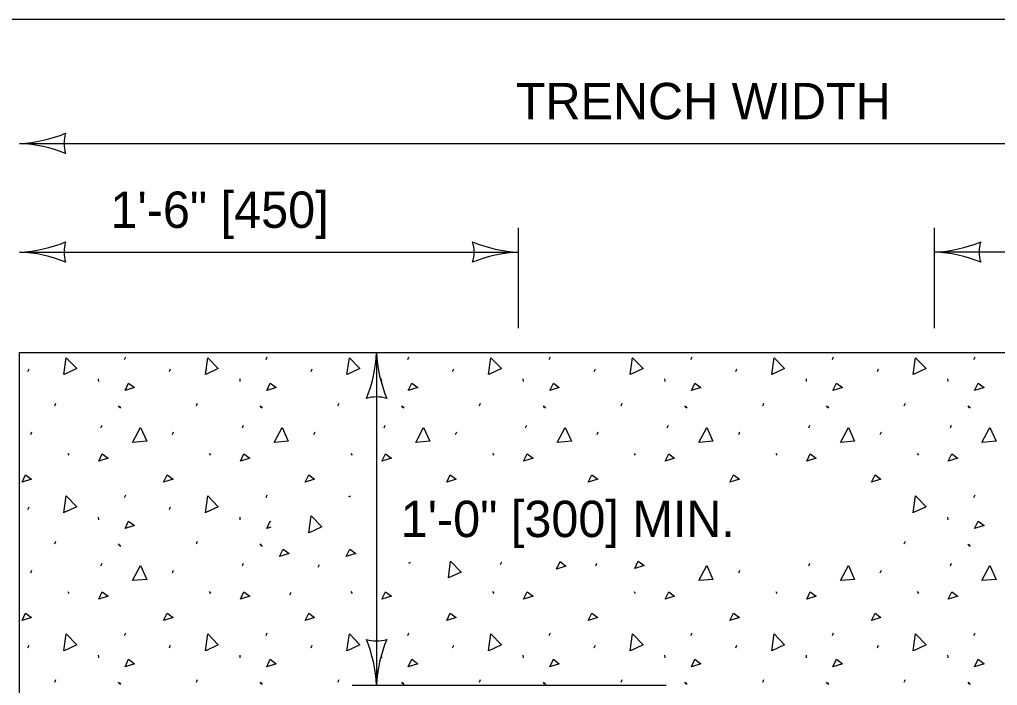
# Model space of a CAD drawing. Extents: x 49991.4 to 50061.4, y 49960.6 to 50011.4.
# Drawn here: x 50012.414 to 50014.03, y 49996.543 to 49997.642 of the extents above; entities that cross this region are included whole.
import ezdxf

# ---------------------------------------------------------------- set-up
doc = ezdxf.new("R2010")
doc.units = 0
for name, color, linetype in [('Level 1', 7, 'Continuous'), ('Level 2', 7, 'Continuous'), ('Level 3', 7, 'Continuous')]:
    doc.layers.add(name, color=color, linetype=linetype)

msp = doc.modelspace()

# ---------------------------------------------------------------- linework, layer by layer
at = {"layer": 'Level 1'}
for p, q in [((50015.4944, 49997.6424), (50011.6711, 49997.6424)), ((50012.4143, 49997.0926), (50014.7511, 49997.0926)), ((50012.4143, 49995.58), (50012.4143, 49997.0926)), ((50012.5878, 49997.0811), (50012.5897, 49997.0855)), ((50012.8217, 49997.0811), (50012.8237, 49997.0855)), ((50013.0557, 49997.0811), (50013.0576, 49997.0855)), ((50013.2896, 49997.0811), (50013.2916, 49997.0855)), ((50013.5236, 49997.0811), (50013.5256, 49997.0855)), ((50013.7576, 49997.0811), (50013.7595, 49997.0855)), ((50013.9915, 49997.0811), (50013.9935, 49997.0855)), ((50012.4281, 49997.0611), (50012.43, 49997.0655)), ((50012.662, 49997.0611), (50012.664, 49997.0655)), ((50012.896, 49997.0611), (50012.8979, 49997.0655)), ((50013.1299, 49997.0611), (50013.1319, 49997.0655)), ((50013.3639, 49997.0611), (50013.3658, 49997.0655)), ((50013.5978, 49997.0611), (50013.5998, 49997.0655)), ((50013.8318, 49997.0611), (50013.8337, 49997.0655)), ((50012.5442, 49997.0488), (50012.5447, 49997.0444)), ((50012.7781, 49997.0488), (50012.7786, 49997.0444)), ((50013.0121, 49997.0488), (50013.0126, 49997.0444)), ((50013.246, 49997.0488), (50013.2465, 49997.0444)), ((50013.48, 49997.0488), (50013.4805, 49997.0444)), ((50013.714, 49997.0488), (50013.7144, 49997.0444)), ((50013.9479, 49997.0488), (50013.9484, 49997.0444)), ((50012.4725, 49997.0044), (50012.4744, 49997.0088)), ((50012.5775, 49997.0044), (50012.5795, 49997.0015)), ((50012.5795, 49997.0033), (50012.5814, 49997.0004)), ((50012.7065, 49997.0044), (50012.7084, 49997.0088)), ((50012.8115, 49997.0044), (50012.8134, 49997.0015)), ((50012.8134, 49997.0033), (50012.8154, 49997.0004)), ((50012.9404, 49997.0044), (50012.9424, 49997.0088)), ((50013.0454, 49997.0044), (50013.0474, 49997.0015)), ((50013.0474, 49997.0033), (50013.0493, 49997.0004)), ((50013.1744, 49997.0044), (50013.1763, 49997.0088)), ((50013.2794, 49997.0044), (50013.2813, 49997.0015)), ((50013.2813, 49997.0033), (50013.2833, 49997.0004)), ((50013.4083, 49997.0044), (50013.4103, 49997.0088)), ((50013.5133, 49997.0044), (50013.5153, 49997.0015)), ((50013.5153, 49997.0033), (50013.5172, 49997.0004)), ((50013.6423, 49997.0044), (50013.6442, 49997.0088)), ((50013.7473, 49997.0044), (50013.7493, 49997.0015)), ((50013.7493, 49997.0033), (50013.7512, 49997.0004)), ((50013.8762, 49997.0044), (50013.8782, 49997.0088)), ((50013.9813, 49997.0044), (50013.9832, 49997.0015)), ((50013.9832, 49997.0033), (50013.9852, 49997.0004)), ((50012.5487, 49996.9682), (50012.5506, 49996.9726)), ((50012.7826, 49996.9682), (50012.7846, 49996.9726)), ((50013.0166, 49996.9682), (50013.0186, 49996.9726)), ((50013.2506, 49996.9682), (50013.2525, 49996.9726)), ((50013.4845, 49996.9682), (50013.4865, 49996.9726)), ((50013.7185, 49996.9682), (50013.7204, 49996.9726)), ((50013.9524, 49996.9682), (50013.9544, 49996.9726)), ((50012.4329, 49996.957), (50012.4349, 49996.9614)), ((50012.6669, 49996.957), (50012.6688, 49996.9614)), ((50012.9008, 49996.957), (50012.9028, 49996.9614)), ((50013.1348, 49996.957), (50013.1368, 49996.9614)), ((50013.3688, 49996.957), (50013.3707, 49996.9614)), ((50013.6027, 49996.957), (50013.6047, 49996.9614)), ((50013.8367, 49996.957), (50013.8386, 49996.9614)), ((50012.494, 49996.9257), (50012.4959, 49996.9228)), ((50012.7279, 49996.9257), (50012.7299, 49996.9228)), ((50012.9619, 49996.9257), (50012.9639, 49996.9228)), ((50013.1959, 49996.9257), (50013.1978, 49996.9228)), ((50013.4298, 49996.9257), (50013.4318, 49996.9228)), ((50013.6638, 49996.9257), (50013.6657, 49996.9228)), ((50013.8977, 49996.9257), (50013.8997, 49996.9228)), ((50012.5878, 49996.853), (50012.5897, 49996.8573)), ((50012.8217, 49996.853), (50012.8237, 49996.8573)), ((50013.9915, 49996.853), (50013.9935, 49996.8573)), ((50012.4281, 49996.8329), (50012.43, 49996.8373)), ((50012.662, 49996.8329), (50012.664, 49996.8373)), ((50012.5442, 49996.8207), (50012.5447, 49996.8163)), ((50012.7781, 49996.8207), (50012.7786, 49996.8163)), ((50013.9479, 49996.8207), (50013.9484, 49996.8163)), ((50012.4725, 49996.7763), (50012.4744, 49996.7807)), ((50012.5775, 49996.7763), (50012.5795, 49996.7733)), ((50012.5795, 49996.7752), (50012.5814, 49996.7722)), ((50012.7065, 49996.7763), (50012.7084, 49996.7807)), ((50012.8115, 49996.7763), (50012.8134, 49996.7733)), ((50012.8134, 49996.7752), (50012.8154, 49996.7722)), ((50013.8762, 49996.7763), (50013.8782, 49996.7807)), ((50013.9813, 49996.7763), (50013.9832, 49996.7733)), ((50013.9832, 49996.7752), (50013.9852, 49996.7722)), ((50012.5487, 49996.7401), (50012.5506, 49996.7445)), ((50012.7826, 49996.7401), (50012.7846, 49996.7445)), ((50012.908, 49996.738), (50012.91, 49996.7424)), ((50013.2092, 49996.7421), (50013.2111, 49996.7465)), ((50013.3666, 49996.7399), (50013.3685, 49996.7443)), ((50013.7185, 49996.7401), (50013.7204, 49996.7445)), ((50013.9524, 49996.7401), (50013.9544, 49996.7445)), ((50012.4329, 49996.7288), (50012.4349, 49996.7332)), ((50012.6669, 49996.7288), (50012.6688, 49996.7332)), ((50013.6027, 49996.7288), (50013.6047, 49996.7332)), ((50013.8367, 49996.7288), (50013.8386, 49996.7332)), ((50012.494, 49996.6976), (50012.4959, 49996.6946)), ((50012.7279, 49996.6976), (50012.7299, 49996.6946)), ((50012.8611, 49996.6922), (50012.8631, 49996.6966)), ((50012.9619, 49996.6976), (50012.9639, 49996.6946)), ((50013.1959, 49996.6976), (50013.1978, 49996.6946)), ((50013.4298, 49996.6976), (50013.4318, 49996.6946)), ((50013.6638, 49996.6976), (50013.6657, 49996.6946)), ((50013.8977, 49996.6976), (50013.8997, 49996.6946)), ((50012.5878, 49996.6248), (50012.5897, 49996.6292)), ((50012.8217, 49996.6248), (50012.8237, 49996.6292)), ((50013.0557, 49996.6248), (50013.0576, 49996.6292)), ((50013.2896, 49996.6248), (50013.2916, 49996.6292)), ((50013.5236, 49996.6248), (50013.5256, 49996.6292)), ((50013.7576, 49996.6248), (50013.7595, 49996.6292)), ((50013.9915, 49996.6248), (50013.9935, 49996.6292)), ((50012.4281, 49996.6048), (50012.43, 49996.6092)), ((50012.662, 49996.6048), (50012.664, 49996.6092)), ((50012.896, 49996.6048), (50012.8979, 49996.6092)), ((50013.1299, 49996.6048), (50013.1319, 49996.6092)), ((50013.3639, 49996.6048), (50013.3658, 49996.6092)), ((50013.5978, 49996.6048), (50013.5998, 49996.6092)), ((50013.8318, 49996.6048), (50013.8337, 49996.6092)), ((50012.5442, 49996.5925), (50012.5447, 49996.5881)), ((50012.7781, 49996.5925), (50012.7786, 49996.5881)), ((50013.0121, 49996.5925), (50013.0126, 49996.5881)), ((50013.246, 49996.5925), (50013.2465, 49996.5881)), ((50013.48, 49996.5925), (50013.4805, 49996.5881)), ((50013.714, 49996.5925), (50013.7144, 49996.5881)), ((50013.9479, 49996.5925), (50013.9484, 49996.5881)), ((50012.4725, 49996.5481), (50012.4744, 49996.5525)), ((50012.5775, 49996.5481), (50012.5795, 49996.5452)), ((50012.7065, 49996.5481), (50012.7084, 49996.5525)), ((50012.8115, 49996.5481), (50012.8134, 49996.5452)), ((50012.9404, 49996.5481), (50012.9424, 49996.5525)), ((50013.0454, 49996.5481), (50013.0474, 49996.5452)), ((50013.1744, 49996.5481), (50013.1763, 49996.5525)), ((50013.2794, 49996.5481), (50013.2813, 49996.5452)), ((50013.4083, 49996.5481), (50013.4103, 49996.5525)), ((50013.5133, 49996.5481), (50013.5153, 49996.5452)), ((50013.6423, 49996.5481), (50013.6442, 49996.5525)), ((50013.7473, 49996.5481), (50013.7493, 49996.5452)), ((50013.8762, 49996.5481), (50013.8782, 49996.5525)), ((50013.9813, 49996.5481), (50013.9832, 49996.5452)), ((50012.5795, 49996.547), (50012.5814, 49996.5441)), ((50012.8134, 49996.547), (50012.8154, 49996.5441)), ((50013.0474, 49996.547), (50013.0493, 49996.5441)), ((50013.2813, 49996.547), (50013.2833, 49996.5441)), ((50013.5153, 49996.547), (50013.5172, 49996.5441)), ((50013.7493, 49996.547), (50013.7512, 49996.5441)), ((50013.9832, 49996.547), (50013.9852, 49996.5441))]:
    msp.add_line(p, q, dxfattribs=at)
for points in [[(50012.4875, 49997.056), (50012.4913, 49997.0839), (50012.5088, 49997.0659), (50012.4879, 49997.0562)], [(50012.7214, 49997.056), (50012.7253, 49997.0839), (50012.7428, 49997.0659), (50012.7219, 49997.0562)], [(50012.9554, 49997.056), (50012.9593, 49997.0839), (50012.9767, 49997.0659), (50012.9558, 49997.0562)], [(50013.1893, 49997.056), (50013.1932, 49997.0839), (50013.2107, 49997.0659), (50013.1898, 49997.0562)], [(50013.4233, 49997.056), (50013.4272, 49997.0839), (50013.4447, 49997.0659), (50013.4238, 49997.0562)], [(50013.6573, 49997.056), (50013.6611, 49997.0839), (50013.6786, 49997.0659), (50013.6577, 49997.0562)], [(50013.8912, 49997.056), (50013.8951, 49997.0839), (50013.9126, 49997.0659), (50013.8917, 49997.0562)], [(50012.5887, 49997.0298), (50012.5946, 49997.042), (50012.6044, 49997.0347), (50012.5887, 49997.0298)], [(50012.8227, 49997.0298), (50012.8286, 49997.042), (50012.8383, 49997.0347), (50012.8227, 49997.0298)], [(50013.0567, 49997.0298), (50013.0625, 49997.042), (50013.0723, 49997.0347), (50013.0567, 49997.0298)], [(50013.2906, 49997.0298), (50013.2965, 49997.042), (50013.3062, 49997.0347), (50013.2906, 49997.0298)], [(50013.5246, 49997.0298), (50013.5304, 49997.042), (50013.5402, 49997.0347), (50013.5246, 49997.0298)], [(50013.7585, 49997.0298), (50013.7644, 49997.042), (50013.7742, 49997.0347), (50013.7585, 49997.0298)], [(50013.9925, 49997.0298), (50013.9984, 49997.042), (50014.0081, 49997.0347), (50013.9925, 49997.0298)], [(50012.601, 49996.9438), (50012.6141, 49996.9687), (50012.6244, 49996.9458), (50012.6014, 49996.9438)], [(50012.8349, 49996.9438), (50012.8481, 49996.9687), (50012.8584, 49996.9458), (50012.8354, 49996.9438)], [(50013.0689, 49996.9438), (50013.0821, 49996.9687), (50013.0923, 49996.9458), (50013.0694, 49996.9438)], [(50013.3028, 49996.9438), (50013.316, 49996.9687), (50013.3263, 49996.9458), (50013.3033, 49996.9438)], [(50013.5368, 49996.9438), (50013.55, 49996.9687), (50013.5602, 49996.9458), (50013.5373, 49996.9438)], [(50013.7707, 49996.9438), (50013.7839, 49996.9687), (50013.7942, 49996.9458), (50013.7712, 49996.9438)], [(50014.0047, 49996.9438), (50014.0179, 49996.9687), (50014.0281, 49996.9458), (50014.0052, 49996.9438)], [(50012.5453, 49996.913), (50012.5511, 49996.9252), (50012.5609, 49996.9179), (50012.5453, 49996.913)], [(50012.7792, 49996.913), (50012.7851, 49996.9252), (50012.7949, 49996.9179), (50012.7792, 49996.913)], [(50013.0132, 49996.913), (50013.019, 49996.9252), (50013.0288, 49996.9179), (50013.0132, 49996.913)], [(50013.2471, 49996.913), (50013.253, 49996.9252), (50013.2628, 49996.9179), (50013.2471, 49996.913)], [(50013.4811, 49996.913), (50013.487, 49996.9252), (50013.4967, 49996.9179), (50013.4811, 49996.913)], [(50013.7151, 49996.913), (50013.7209, 49996.9252), (50013.7307, 49996.9179), (50013.7151, 49996.913)], [(50013.949, 49996.913), (50013.9549, 49996.9252), (50013.9646, 49996.9179), (50013.949, 49996.913)], [(50012.4184, 49996.8781), (50012.4242, 49996.8903), (50012.434, 49996.883), (50012.4184, 49996.8781)], [(50012.6523, 49996.8781), (50012.6582, 49996.8903), (50012.668, 49996.883), (50012.6523, 49996.8781)], [(50012.8863, 49996.8781), (50012.8922, 49996.8903), (50012.9019, 49996.883), (50012.8863, 49996.8781)], [(50013.1203, 49996.8781), (50013.1261, 49996.8903), (50013.1359, 49996.883), (50013.1203, 49996.8781)], [(50013.3542, 49996.8781), (50013.3601, 49996.8903), (50013.3698, 49996.883), (50013.3542, 49996.8781)], [(50013.5882, 49996.8781), (50013.594, 49996.8903), (50013.6038, 49996.883), (50013.5882, 49996.8781)], [(50013.8221, 49996.8781), (50013.828, 49996.8903), (50013.8378, 49996.883), (50013.8221, 49996.8781)], [(50012.4875, 49996.8279), (50012.4913, 49996.8558), (50012.5088, 49996.8377), (50012.4879, 49996.828)], [(50012.7214, 49996.8279), (50012.7253, 49996.8558), (50012.7428, 49996.8377), (50012.7219, 49996.828)], [(50012.959, 49996.8543), (50012.9593, 49996.8558), (50012.9607, 49996.8543)], [(50013.8912, 49996.8279), (50013.8951, 49996.8558), (50013.9126, 49996.8377), (50013.8917, 49996.828)], [(50012.8922, 49996.7946), (50012.8961, 49996.8225), (50012.9136, 49996.8044), (50012.8927, 49996.7948)], [(50012.5887, 49996.8017), (50012.5946, 49996.8139), (50012.6044, 49996.8066), (50012.5887, 49996.8017)], [(50012.8227, 49996.8017), (50012.8286, 49996.8139), (50012.8295, 49996.8132)], [(50013.9925, 49996.8017), (50013.9984, 49996.8139), (50014.0081, 49996.8066), (50013.9925, 49996.8017)], [(50012.8295, 49996.8038), (50012.8227, 49996.8017)], [(50012.8441, 49996.7556), (50012.85, 49996.7678), (50012.8597, 49996.7604), (50012.8441, 49996.7556)], [(50012.9541, 49996.7556), (50012.96, 49996.7678), (50012.9698, 49996.7604), (50012.9541, 49996.7556)], [(50013.0583, 49996.7445), (50013.0585, 49996.746), (50013.06, 49996.7445)], [(50013.1229, 49996.7201), (50013.1267, 49996.748), (50013.1442, 49996.7299), (50013.1233, 49996.7202)], [(50013.3016, 49996.7347), (50013.3075, 49996.747), (50013.3172, 49996.7396), (50013.3016, 49996.7347)], [(50013.4309, 49996.7358), (50013.4367, 49996.748), (50013.4465, 49996.7407), (50013.4309, 49996.7358)], [(50012.601, 49996.7157), (50012.6141, 49996.7406), (50012.6244, 49996.7176), (50012.6014, 49996.7157)], [(50013.5368, 49996.7157), (50013.55, 49996.7406), (50013.5602, 49996.7176), (50013.5373, 49996.7157)], [(50013.7707, 49996.7157), (50013.7839, 49996.7406), (50013.7942, 49996.7176), (50013.7712, 49996.7157)], [(50014.0047, 49996.7157), (50014.0179, 49996.7406), (50014.0281, 49996.7176), (50014.0052, 49996.7157)], [(50012.5453, 49996.6849), (50012.5511, 49996.6971), (50012.5609, 49996.6898), (50012.5453, 49996.6849)], [(50012.7792, 49996.6849), (50012.7851, 49996.6971), (50012.7949, 49996.6898), (50012.7792, 49996.6849)], [(50013.0132, 49996.6849), (50013.019, 49996.6971), (50013.0288, 49996.6898), (50013.0132, 49996.6849)], [(50013.2471, 49996.6849), (50013.253, 49996.6971), (50013.2628, 49996.6898), (50013.2471, 49996.6849)], [(50013.4811, 49996.6849), (50013.487, 49996.6971), (50013.4967, 49996.6898), (50013.4811, 49996.6849)], [(50013.7151, 49996.6849), (50013.7209, 49996.6971), (50013.7307, 49996.6898), (50013.7151, 49996.6849)], [(50013.949, 49996.6849), (50013.9549, 49996.6971), (50013.9646, 49996.6898), (50013.949, 49996.6849)], [(50012.4184, 49996.65), (50012.4242, 49996.6622), (50012.434, 49996.6549), (50012.4184, 49996.65)], [(50012.6523, 49996.65), (50012.6582, 49996.6622), (50012.668, 49996.6549), (50012.6523, 49996.65)], [(50012.8863, 49996.65), (50012.8922, 49996.6622), (50012.9019, 49996.6549), (50012.8863, 49996.65)], [(50013.1203, 49996.65), (50013.1261, 49996.6622), (50013.1359, 49996.6549), (50013.1203, 49996.65)], [(50013.3542, 49996.65), (50013.3601, 49996.6622), (50013.3698, 49996.6549), (50013.3542, 49996.65)], [(50013.5882, 49996.65), (50013.594, 49996.6622), (50013.6038, 49996.6549), (50013.5882, 49996.65)], [(50013.8221, 49996.65), (50013.828, 49996.6622), (50013.8378, 49996.6549), (50013.8221, 49996.65)], [(50012.4875, 49996.5997), (50012.4913, 49996.6276), (50012.5088, 49996.6096), (50012.4879, 49996.5999)], [(50012.7214, 49996.5997), (50012.7253, 49996.6276), (50012.7428, 49996.6096), (50012.7219, 49996.5999)], [(50012.9554, 49996.5997), (50012.9593, 49996.6276), (50012.9767, 49996.6096), (50012.9558, 49996.5999)], [(50013.1893, 49996.5997), (50013.1932, 49996.6276), (50013.2107, 49996.6096), (50013.1898, 49996.5999)], [(50013.4233, 49996.5997), (50013.4272, 49996.6276), (50013.4447, 49996.6096), (50013.4238, 49996.5999)], [(50013.6573, 49996.5997), (50013.6611, 49996.6276), (50013.6786, 49996.6096), (50013.6577, 49996.5999)], [(50013.8912, 49996.5997), (50013.8951, 49996.6276), (50013.9126, 49996.6096), (50013.8917, 49996.5999)], [(50012.5887, 49996.5735), (50012.5946, 49996.5857), (50012.6044, 49996.5784), (50012.5887, 49996.5735)], [(50012.8227, 49996.5735), (50012.8286, 49996.5857), (50012.8383, 49996.5784), (50012.8227, 49996.5735)], [(50013.0567, 49996.5735), (50013.0625, 49996.5857), (50013.0723, 49996.5784), (50013.0567, 49996.5735)], [(50013.2906, 49996.5735), (50013.2965, 49996.5857), (50013.3062, 49996.5784), (50013.2906, 49996.5735)], [(50013.5246, 49996.5735), (50013.5304, 49996.5857), (50013.5402, 49996.5784), (50013.5246, 49996.5735)], [(50013.7585, 49996.5735), (50013.7644, 49996.5857), (50013.7742, 49996.5784), (50013.7585, 49996.5735)], [(50013.9925, 49996.5735), (50013.9984, 49996.5857), (50014.0081, 49996.5784), (50013.9925, 49996.5735)]]:
    msp.add_lwpolyline(points, dxfattribs=at)
at = {"layer": 'Level 3'}
for p, q in [((50012.4143, 49997.4378), (50014.7511, 49997.4378)), ((50013.239, 49997.1326), (50013.239, 49997.2983)), ((50013.9265, 49997.1326), (50013.9265, 49997.2983)), ((50012.4143, 49997.2583), (50013.239, 49997.2583)), ((50014.7511, 49997.2583), (50013.9265, 49997.2583)), ((50013.0042, 49997.0926), (50013.0042, 49996.5426)), ((50013.4827, 49996.5426), (50012.9642, 49996.5426))]:
    msp.add_line(p, q, dxfattribs=at)
for centre, radius, start, end in [((50012.4029, 49997.6705), 0.233, 272.8273, 292.0772), ((50012.5426, 49997.4378), 0.0548, 162.1388, 197.8612), ((50012.4052, 49997.2156), 0.2223, 67.456, 87.6395), ((50012.4029, 49997.491), 0.233, 272.8273, 292.0772), ((50012.5426, 49997.2583), 0.0548, 162.1388, 197.8612), ((50013.2481, 49997.4804), 0.2223, 247.456, 267.6395), ((50013.1108, 49997.2583), 0.0548, 342.1388, 17.8612), ((50013.915, 49997.491), 0.233, 272.8273, 292.0772), ((50014.0547, 49997.2583), 0.0548, 162.1388, 197.8612), ((50012.4052, 49997.0362), 0.2223, 67.456, 87.6395), ((50013.2505, 49997.0256), 0.233, 92.8273, 112.0772), ((50013.9173, 49997.0362), 0.2223, 67.456, 87.6395), ((50012.7821, 49997.1017), 0.2223, 337.456, 357.6395), ((50013.2369, 49997.1041), 0.233, 182.8273, 202.0772), ((50013.0042, 49996.9643), 0.0548, 72.1388, 107.8612), ((50013.0042, 49996.6708), 0.0548, 252.1388, 287.8612), ((50012.7715, 49996.5311), 0.233, 2.8273, 22.0772), ((50013.2264, 49996.5334), 0.2223, 157.456, 177.6395)]:
    msp.add_arc(centre, radius, start, end, dxfattribs=at)

# ---------------------------------------------------------------- texts
at = {"layer": 'Level 2'}
for s, p in [('TRENCH WIDTH', (50013.2344, 49997.4778)), ('1\'-6" [450]', (50012.5646, 49997.2983)), ('1\'-0" [300] MIN.', (50013.0442, 49996.7876))]:
    msp.add_text(s, height=0.06, dxfattribs=at).set_placement(p)

doc.saveas('drawing.dxf')
